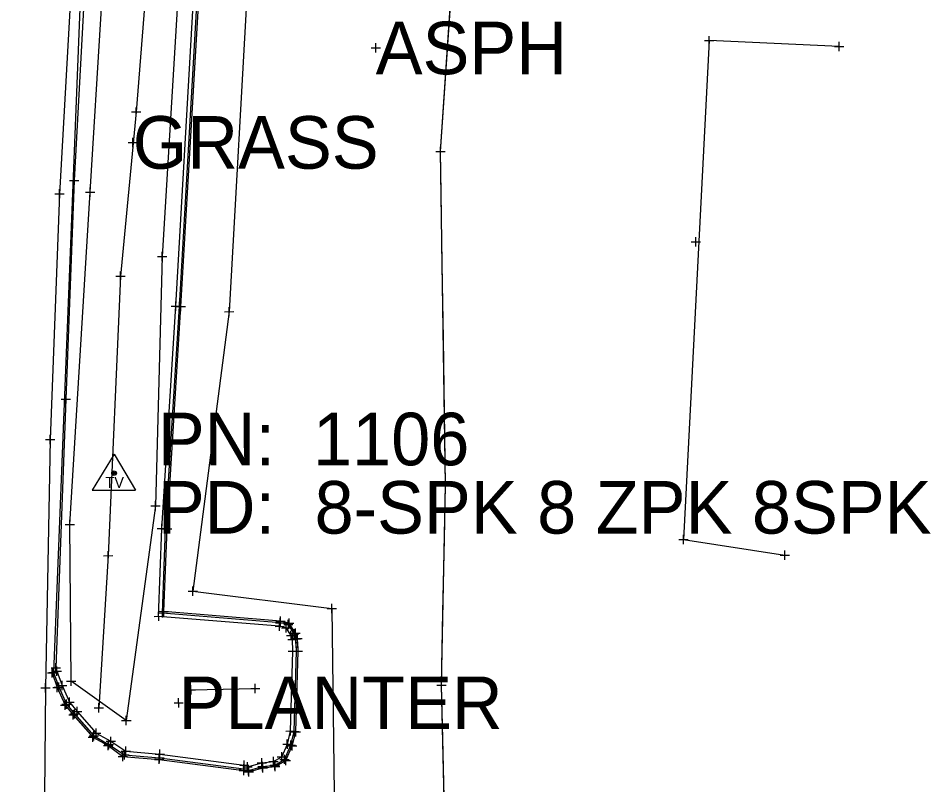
# Model space of a CAD drawing. Extents: x -1 to 1157254, y -1 to 2021979.
# Drawn here: x 1151704.9 to 1151829.9, y 2019737 to 2019842 of the extents above; entities that cross this region are included whole.
import ezdxf

# ---------------------------------------------------------------- set-up
doc = ezdxf.new("R2010")
doc.units = 0
for name, color, linetype in [('S_BREAKLINE', 7, 'Continuous'), ('S_BUILDING_ANNOT', 7, 'Continuous'), ('S_CTL_TABLE', 7, 'Continuous'), ('S_DTM_PAVEMENT', 7, 'Continuous'), ('S_EDGE_BITUMINOUS_ANNOT', 7, 'Continuous'), ('S_EDGE_CONCRETE', 7, 'Continuous'), ('S_EDGE_PAVEMENT', 7, 'Continuous'), ('S_EDGE_PAVEMENT_ANNOT', 7, 'Continuous'), ('S_ENV_CONSTRAINT', 7, 'Continuous'), ('S_FLAG_POLE_ANNOT', 7, 'Continuous'), ('S_GAS_PUMP_ISLAND_ANNOT', 7, 'Continuous'), ('S_GAS_UTILITIES_ANNOT', 7, 'Continuous'), ('S_GATE', 7, 'Continuous')]:
    doc.layers.add(name, color=color, linetype=linetype)

msp = doc.modelspace()

# ---------------------------------------------------------------- linework, layer by layer
at = {"layer": 'S_BREAKLINE'}
for p, q in [((1151717.99, 2019782.25), (1151714.98, 2019777.3)), ((1151717.99, 2019782.25), (1151720.94, 2019777.3)), ((1151714.98, 2019777.3), (1151720.94, 2019777.3))]:
    msp.add_line(p, q, dxfattribs=at)
for radius in [0.311, 0.183, 0.103]:
    msp.add_circle((1151717.99, 2019779.64), radius, dxfattribs=at)
at = {"layer": 'S_BUILDING_ANNOT'}
for p, q in [((1151799.54, 2019838.25), (1151799.54, 2019839.52)), ((1151753.84, 2019837.26), (1151753.84, 2019838.53)), ((1151798.9, 2019838.89), (1151800.18, 2019838.89)), ((1151799.54, 2019838.89), (1151799.54, 2019838.89)), ((1151817.36, 2019837.47), (1151817.35, 2019838.74)), ((1151753.21, 2019837.89), (1151754.48, 2019837.89)), ((1151753.84, 2019837.89), (1151753.84, 2019837.89)), ((1151816.72, 2019838.1), (1151817.99, 2019838.1)), ((1151817.36, 2019838.1), (1151817.36, 2019838.1)), ((1151719.9, 2019824.94), (1151721.18, 2019824.95)), ((1151720.54, 2019824.31), (1151720.54, 2019825.58)), ((1151720.54, 2019824.95), (1151720.54, 2019824.95)), ((1151711.87, 2019819.72), (1151713.14, 2019819.72)), ((1151712.5, 2019819.08), (1151712.5, 2019820.36)), ((1151712.5, 2019819.72), (1151712.5, 2019819.72)), ((1151710.53, 2019817.26), (1151710.53, 2019818.53)), ((1151709.89, 2019817.9), (1151711.17, 2019817.9)), ((1151710.53, 2019817.9), (1151710.53, 2019817.9)), ((1151797.7, 2019810.7), (1151797.7, 2019811.97)), ((1151797.07, 2019811.34), (1151798.34, 2019811.34)), ((1151797.7, 2019811.34), (1151797.7, 2019811.34)), ((1151726.45, 2019801.88), (1151726.45, 2019803.15)), ((1151726.95, 2019801.85), (1151726.95, 2019803.12)), ((1151727.15, 2019801.84), (1151727.15, 2019803.11)), ((1151725.82, 2019802.51), (1151727.09, 2019802.51)), ((1151726.32, 2019802.48), (1151727.59, 2019802.48)), ((1151726.45, 2019802.51), (1151726.45, 2019802.51)), ((1151726.51, 2019802.47), (1151727.79, 2019802.47)), ((1151726.95, 2019802.48), (1151726.95, 2019802.48)), ((1151727.15, 2019802.47), (1151727.15, 2019802.47)), ((1151710.74, 2019789.77), (1151712.02, 2019789.77)), ((1151711.38, 2019789.13), (1151711.38, 2019790.41)), ((1151711.38, 2019789.77), (1151711.38, 2019789.77)), ((1151709.24, 2019783.62), (1151709.24, 2019784.89)), ((1151708.61, 2019784.25), (1151709.88, 2019784.26)), ((1151709.24, 2019784.25), (1151709.24, 2019784.25)), ((1151723.91, 2019772.05), (1151725.19, 2019772.05)), ((1151724.41, 2019772.03), (1151725.69, 2019772.03)), ((1151724.55, 2019771.42), (1151724.55, 2019772.69)), ((1151724.55, 2019772.05), (1151724.55, 2019772.05)), ((1151724.61, 2019772.02), (1151725.89, 2019772.02)), ((1151725.05, 2019771.39), (1151725.05, 2019772.66)), ((1151725.05, 2019772.03), (1151725.05, 2019772.03)), ((1151725.25, 2019771.38), (1151725.25, 2019772.65)), ((1151725.25, 2019772.02), (1151725.25, 2019772.02)), ((1151796.01, 2019769.93), (1151796.01, 2019771.2)), ((1151795.38, 2019770.56), (1151796.65, 2019770.56)), ((1151796.01, 2019770.56), (1151796.01, 2019770.56)), ((1151809.28, 2019768.42), (1151810.56, 2019768.42)), ((1151809.92, 2019767.78), (1151809.92, 2019769.06)), ((1151809.92, 2019768.42), (1151809.92, 2019768.42)), ((1151724.11, 2019759.39), (1151724.1, 2019760.66)), ((1151724.19, 2019760.67), (1151725.47, 2019760.67)), ((1151724.62, 2019759.85), (1151724.62, 2019761.12)), ((1151724.83, 2019760.03), (1151724.83, 2019761.3)), ((1151724.83, 2019760.67), (1151724.83, 2019760.67)), ((1151723.47, 2019760.02), (1151724.74, 2019760.03)), ((1151723.99, 2019760.48), (1151725.26, 2019760.49)), ((1151724.1, 2019760.02), (1151724.1, 2019760.02)), ((1151724.62, 2019760.48), (1151724.62, 2019760.48)), ((1151740.15, 2019759.35), (1151741.42, 2019759.35)), ((1151740.76, 2019758.52), (1151740.76, 2019759.79)), ((1151740.79, 2019758.71), (1151740.78, 2019759.99)), ((1151740.79, 2019759.35), (1151740.79, 2019759.35)), ((1151741.88, 2019758.28), (1151741.87, 2019759.55)), ((1151742, 2019758.45), (1151742, 2019759.73)), ((1151740.05, 2019758.65), (1151741.32, 2019758.66)), ((1151740.12, 2019759.15), (1151741.39, 2019759.15)), ((1151740.68, 2019758.02), (1151740.68, 2019759.29)), ((1151740.68, 2019758.66), (1151740.68, 2019758.66)), ((1151740.76, 2019759.15), (1151740.76, 2019759.15)), ((1151740.93, 2019758.47), (1151742.2, 2019758.47)), ((1151741.24, 2019758.91), (1151742.51, 2019758.91)), ((1151741.36, 2019759.09), (1151742.64, 2019759.09)), ((1151741.57, 2019757.83), (1151741.56, 2019759.1)), ((1151741.56, 2019758.47), (1151741.56, 2019758.47)), ((1151741.88, 2019758.91), (1151741.88, 2019758.91)), ((1151742, 2019759.09), (1151742, 2019759.09)), ((1151742.69, 2019756.98), (1151742.69, 2019758.26)), ((1151742.87, 2019757.07), (1151742.87, 2019758.34)), ((1151741.6, 2019757.4), (1151742.87, 2019757.4)), ((1151741.79, 2019756.84), (1151743.06, 2019756.84)), ((1151742.06, 2019757.62), (1151743.33, 2019757.62)), ((1151742.24, 2019756.77), (1151742.23, 2019758.04)), ((1151742.24, 2019757.7), (1151743.51, 2019757.71)), ((1151742.24, 2019757.4), (1151742.24, 2019757.4)), ((1151742.28, 2019756.93), (1151743.55, 2019756.94)), ((1151742.42, 2019756.21), (1151742.42, 2019757.48)), ((1151742.42, 2019756.84), (1151742.42, 2019756.84)), ((1151742.48, 2019756.97), (1151743.75, 2019756.97)), ((1151742.69, 2019757.62), (1151742.69, 2019757.62)), ((1151742.87, 2019757.7), (1151742.87, 2019757.7)), ((1151742.92, 2019756.3), (1151742.92, 2019757.57)), ((1151742.92, 2019756.93), (1151742.92, 2019756.93)), ((1151743.12, 2019756.34), (1151743.12, 2019757.61)), ((1151743.12, 2019756.97), (1151743.12, 2019756.97)), ((1151742.5, 2019754.62), (1151742.5, 2019755.89)), ((1151743, 2019754.62), (1151743, 2019755.89)), ((1151743.2, 2019754.62), (1151743.2, 2019755.9)), ((1151741.86, 2019755.25), (1151743.13, 2019755.26)), ((1151742.36, 2019755.26), (1151743.63, 2019755.26)), ((1151742.5, 2019755.25), (1151742.5, 2019755.25)), ((1151742.56, 2019755.26), (1151743.83, 2019755.26)), ((1151743, 2019755.26), (1151743, 2019755.26)), ((1151743.2, 2019755.26), (1151743.2, 2019755.26)), ((1151709.99, 2019752.33), (1151709.99, 2019753.6)), ((1151710.16, 2019751.88), (1151710.16, 2019753.15)), ((1151708.87, 2019752.28), (1151710.14, 2019752.29)), ((1151709.05, 2019752.35), (1151710.33, 2019752.35)), ((1151709.36, 2019752.96), (1151710.63, 2019752.97)), ((1151709.5, 2019751.65), (1151709.5, 2019752.92)), ((1151709.5, 2019752.29), (1151709.5, 2019752.29)), ((1151709.53, 2019752.52), (1151710.8, 2019752.52)), ((1151709.69, 2019751.72), (1151709.69, 2019752.99)), ((1151709.69, 2019752.35), (1151709.69, 2019752.35)), ((1151709.99, 2019752.96), (1151709.99, 2019752.96)), ((1151710.16, 2019752.52), (1151710.16, 2019752.52)), ((1151708.59, 2019749.61), (1151708.58, 2019750.89)), ((1151710.21, 2019749.64), (1151710.21, 2019750.91)), ((1151710.4, 2019749.71), (1151710.4, 2019750.98)), ((1151710.86, 2019749.9), (1151710.86, 2019751.17)), ((1151728.54, 2019749.34), (1151728.53, 2019750.61)), ((1151737.34, 2019749.49), (1151737.34, 2019750.76)), ((1151707.95, 2019750.25), (1151709.22, 2019750.25)), ((1151708.59, 2019750.25), (1151708.59, 2019750.25)), ((1151709.58, 2019750.27), (1151710.85, 2019750.27)), ((1151709.76, 2019750.34), (1151711.04, 2019750.35)), ((1151710.21, 2019750.27), (1151710.21, 2019750.27)), ((1151710.23, 2019750.53), (1151711.5, 2019750.53)), ((1151710.4, 2019750.35), (1151710.4, 2019750.35)), ((1151710.86, 2019750.53), (1151710.86, 2019750.53)), ((1151727.9, 2019749.97), (1151729.17, 2019749.98)), ((1151728.54, 2019749.97), (1151728.54, 2019749.97)), ((1151736.71, 2019750.13), (1151737.98, 2019750.13)), ((1151737.34, 2019750.13), (1151737.34, 2019750.13)), ((1151711.25, 2019748.25), (1151712.52, 2019748.25)), ((1151711.28, 2019747.24), (1151711.28, 2019748.51)), ((1151711.45, 2019747.35), (1151711.45, 2019748.62)), ((1151711.88, 2019747.61), (1151711.88, 2019748.89)), ((1151711.88, 2019748.25), (1151711.88, 2019748.25)), ((1151726.21, 2019748.18), (1151727.48, 2019748.18)), ((1151726.85, 2019747.54), (1151726.84, 2019748.82)), ((1151726.84, 2019748.18), (1151726.84, 2019748.18)), ((1151710.65, 2019747.88), (1151711.92, 2019747.88)), ((1151710.82, 2019747.98), (1151712.09, 2019747.99)), ((1151711.28, 2019747.88), (1151711.28, 2019747.88)), ((1151711.45, 2019747.98), (1151711.45, 2019747.98)), ((1151712.3, 2019746.97), (1151713.57, 2019746.97)), ((1151712.4, 2019745.88), (1151712.4, 2019747.15)), ((1151712.56, 2019746.01), (1151712.55, 2019747.28)), ((1151712.94, 2019746.34), (1151712.93, 2019747.61)), ((1151712.93, 2019746.97), (1151712.93, 2019746.97)), ((1151711.77, 2019746.52), (1151713.04, 2019746.52)), ((1151711.92, 2019746.65), (1151713.19, 2019746.65)), ((1151712.4, 2019746.52), (1151712.4, 2019746.52)), ((1151712.55, 2019746.65), (1151712.55, 2019746.65)), ((1151715.55, 2019743.4), (1151715.54, 2019744.67)), ((1151741.55, 2019744.31), (1151742.83, 2019744.32)), ((1151742.19, 2019743.68), (1151742.19, 2019744.95)), ((1151742.69, 2019743.61), (1151742.69, 2019744.88)), ((1151742.89, 2019743.58), (1151742.89, 2019744.85)), ((1151714.46, 2019743.48), (1151715.73, 2019743.48)), ((1151714.59, 2019743.64), (1151715.86, 2019743.64)), ((1151714.91, 2019744.03), (1151716.18, 2019744.04)), ((1151715.1, 2019742.85), (1151715.1, 2019744.12)), ((1151715.1, 2019743.48), (1151715.1, 2019743.48)), ((1151715.23, 2019743), (1151715.22, 2019744.28)), ((1151715.23, 2019743.64), (1151715.23, 2019743.64)), ((1151715.54, 2019744.04), (1151715.54, 2019744.04)), ((1151717.28, 2019741.85), (1151717.28, 2019743.12)), ((1151717.54, 2019742.27), (1151717.54, 2019743.54)), ((1151741.74, 2019741.89), (1151741.73, 2019743.16)), ((1151742.05, 2019744.24), (1151743.32, 2019744.25)), ((1151742.19, 2019744.31), (1151742.19, 2019744.31)), ((1151742.25, 2019744.22), (1151743.52, 2019744.22)), ((1151742.69, 2019744.24), (1151742.69, 2019744.24)), ((1151742.89, 2019744.22), (1151742.89, 2019744.22)), ((1151716.54, 2019742.31), (1151717.81, 2019742.31)), ((1151716.64, 2019742.48), (1151717.91, 2019742.48)), ((1151716.9, 2019742.91), (1151718.17, 2019742.91)), ((1151717.17, 2019741.67), (1151717.17, 2019742.95)), ((1151717.17, 2019742.31), (1151717.17, 2019742.31)), ((1151717.28, 2019742.48), (1151717.28, 2019742.48)), ((1151717.54, 2019742.91), (1151717.54, 2019742.91)), ((1151719.58, 2019740.91), (1151719.58, 2019742.18)), ((1151741.1, 2019742.53), (1151742.37, 2019742.53)), ((1151741.57, 2019742.36), (1151742.85, 2019742.37)), ((1151741.74, 2019742.53), (1151741.74, 2019742.53)), ((1151741.76, 2019742.3), (1151743.04, 2019742.3)), ((1151742.21, 2019741.73), (1151742.21, 2019743)), ((1151742.21, 2019742.37), (1151742.21, 2019742.37)), ((1151742.4, 2019741.66), (1151742.4, 2019742.94)), ((1151742.4, 2019742.3), (1151742.4, 2019742.3)), ((1151718.56, 2019740.82), (1151719.83, 2019740.82)), ((1151718.78, 2019741.06), (1151720.05, 2019741.06)), ((1151718.95, 2019741.54), (1151720.22, 2019741.55)), ((1151719.2, 2019740.19), (1151719.19, 2019741.46)), ((1151719.19, 2019740.82), (1151719.19, 2019740.82)), ((1151719.41, 2019740.42), (1151719.41, 2019741.69)), ((1151719.41, 2019741.06), (1151719.41, 2019741.06)), ((1151719.58, 2019741.55), (1151719.58, 2019741.55)), ((1151723.57, 2019740.63), (1151724.84, 2019740.63)), ((1151723.63, 2019741.13), (1151724.9, 2019741.13)), ((1151724.19, 2019739.8), (1151724.19, 2019741.07)), ((1151724.21, 2019740), (1151724.21, 2019741.27)), ((1151724.21, 2019740.63), (1151724.21, 2019740.63)), ((1151724.26, 2019740.49), (1151724.26, 2019741.77)), ((1151724.26, 2019741.13), (1151724.26, 2019741.13)), ((1151738.23, 2019739.32), (1151738.23, 2019740.59)), ((1151739.85, 2019739.48), (1151739.85, 2019740.76)), ((1151740.33, 2019740.78), (1151741.6, 2019740.78)), ((1151740.97, 2019740.14), (1151740.97, 2019741.42)), ((1151740.97, 2019740.78), (1151740.97, 2019740.78)), ((1151741.36, 2019739.8), (1151741.36, 2019741.07)), ((1151741.52, 2019739.66), (1151741.52, 2019740.93)), ((1151723.55, 2019740.43), (1151724.82, 2019740.43)), ((1151724.19, 2019740.43), (1151724.19, 2019740.43)), ((1151735.21, 2019739.62), (1151736.48, 2019739.63)), ((1151735.64, 2019739.4), (1151736.91, 2019739.4)), ((1151735.75, 2019738.29), (1151735.75, 2019739.57)), ((1151735.78, 2019738.49), (1151735.78, 2019739.76)), ((1151735.84, 2019738.99), (1151735.84, 2019740.26)), ((1151735.84, 2019739.62), (1151735.84, 2019739.62)), ((1151736.27, 2019738.76), (1151736.27, 2019740.04)), ((1151736.27, 2019739.4), (1151736.27, 2019739.4)), ((1151736.41, 2019738.28), (1151736.41, 2019739.55)), ((1151736.47, 2019738.09), (1151736.46, 2019739.36)), ((1151737.6, 2019739.96), (1151738.87, 2019739.96)), ((1151737.69, 2019739.46), (1151738.96, 2019739.47)), ((1151738.23, 2019739.96), (1151738.23, 2019739.96)), ((1151738.33, 2019738.83), (1151738.33, 2019740.1)), ((1151738.33, 2019739.47), (1151738.33, 2019739.47)), ((1151738.37, 2019738.63), (1151738.36, 2019739.9)), ((1151739.21, 2019740.12), (1151740.48, 2019740.12)), ((1151739.37, 2019739.63), (1151740.64, 2019739.64)), ((1151739.43, 2019739.44), (1151740.71, 2019739.44)), ((1151739.85, 2019740.12), (1151739.85, 2019740.12)), ((1151740.01, 2019739), (1151740, 2019740.27)), ((1151740.01, 2019739.63), (1151740.01, 2019739.63)), ((1151740.07, 2019738.8), (1151740.07, 2019740.08)), ((1151740.07, 2019739.44), (1151740.07, 2019739.44)), ((1151740.72, 2019740.43), (1151742, 2019740.43)), ((1151740.88, 2019740.29), (1151742.15, 2019740.29)), ((1151741.36, 2019740.43), (1151741.36, 2019740.43)), ((1151741.52, 2019740.29), (1151741.52, 2019740.29)), ((1151735.12, 2019738.93), (1151736.39, 2019738.93)), ((1151735.14, 2019739.13), (1151736.41, 2019739.13)), ((1151735.75, 2019738.93), (1151735.75, 2019738.93)), ((1151735.77, 2019738.92), (1151737.05, 2019738.92)), ((1151735.78, 2019739.13), (1151735.78, 2019739.13)), ((1151735.83, 2019738.72), (1151737.1, 2019738.73)), ((1151736.41, 2019738.92), (1151736.41, 2019738.92)), ((1151736.47, 2019738.73), (1151736.47, 2019738.73)), ((1151737.73, 2019739.27), (1151739, 2019739.27)), ((1151738.36, 2019739.27), (1151738.36, 2019739.27))]:
    msp.add_line(p, q, dxfattribs=at)
at = {"layer": 'S_CTL_TABLE'}
for p, q in [((1151721.03, 2019828.48), (1151721.02, 2019829.75)), ((1151720.39, 2019829.12), (1151721.66, 2019829.12)), ((1151721.02, 2019829.12), (1151721.02, 2019829.12)), ((1151762.73, 2019823.08), (1151762.73, 2019824.36)), ((1151762.1, 2019823.72), (1151763.37, 2019823.72)), ((1151762.73, 2019823.72), (1151762.73, 2019823.72)), ((1151714.08, 2019818.15), (1151715.35, 2019818.15)), ((1151714.72, 2019817.51), (1151714.72, 2019818.79)), ((1151714.72, 2019818.15), (1151714.72, 2019818.15)), ((1151724.6, 2019808.68), (1151724.59, 2019809.95)), ((1151723.96, 2019809.31), (1151725.23, 2019809.32)), ((1151724.6, 2019809.32), (1151724.6, 2019809.32)), ((1151718.89, 2019805.98), (1151718.89, 2019807.26)), ((1151718.25, 2019806.62), (1151719.53, 2019806.62)), ((1151718.89, 2019806.62), (1151718.89, 2019806.62)), ((1151733.75, 2019801.13), (1151733.75, 2019802.4)), ((1151733.11, 2019801.76), (1151734.38, 2019801.77)), ((1151733.75, 2019801.77), (1151733.75, 2019801.77)), ((1151763.43, 2019777.41), (1151763.43, 2019778.69)), ((1151762.79, 2019778.05), (1151764.06, 2019778.05)), ((1151763.43, 2019778.05), (1151763.43, 2019778.05)), ((1151723.68, 2019774.52), (1151723.67, 2019775.8)), ((1151723.04, 2019775.16), (1151724.31, 2019775.16)), ((1151723.67, 2019775.16), (1151723.67, 2019775.16)), ((1151711.94, 2019771.96), (1151711.94, 2019773.23)), ((1151711.31, 2019772.6), (1151712.58, 2019772.6)), ((1151711.94, 2019772.6), (1151711.94, 2019772.6)), ((1151716.56, 2019768.33), (1151717.83, 2019768.34)), ((1151717.2, 2019767.7), (1151717.19, 2019768.97)), ((1151717.2, 2019768.34), (1151717.2, 2019768.34)), ((1151728.14, 2019763.49), (1151729.41, 2019763.49)), ((1151728.78, 2019762.85), (1151728.77, 2019764.13)), ((1151728.77, 2019763.49), (1151728.77, 2019763.49)), ((1151747.21, 2019761.12), (1151748.48, 2019761.12)), ((1151747.84, 2019760.48), (1151747.84, 2019761.76)), ((1151747.84, 2019761.12), (1151747.84, 2019761.12)), ((1151711.47, 2019751.13), (1151712.74, 2019751.13)), ((1151712.11, 2019750.5), (1151712.11, 2019751.77)), ((1151712.11, 2019751.13), (1151712.11, 2019751.13)), ((1151762.22, 2019750.6), (1151763.49, 2019750.61)), ((1151762.86, 2019749.97), (1151762.85, 2019751.24)), ((1151762.86, 2019750.61), (1151762.86, 2019750.61)), ((1151715.9, 2019746.84), (1151715.9, 2019748.11)), ((1151715.26, 2019747.47), (1151716.53, 2019747.47)), ((1151715.9, 2019747.47), (1151715.9, 2019747.47)), ((1151719.03, 2019745.76), (1151720.31, 2019745.77)), ((1151719.67, 2019745.13), (1151719.67, 2019746.4)), ((1151719.67, 2019745.76), (1151719.67, 2019745.76))]:
    msp.add_line(p, q, dxfattribs=at)
at = {"layer": 'S_DTM_PAVEMENT'}
msp.add_lwpolyline([(1151728.54, 2019749.97), (1151737.34, 2019750.13)], dxfattribs=at)
at = {"layer": 'S_EDGE_BITUMINOUS_ANNOT'}
for points in [[(1151729.38, 2019894.61), (1151725.75, 2019887.85), (1151723.93, 2019866.05), (1151721.02, 2019829.12), (1151718.89, 2019806.62), (1151717.2, 2019768.34), (1151715.9, 2019747.47)], [(1151764.61, 2019691.37), (1151763.49, 2019723.26), (1151762.86, 2019750.61), (1151763.43, 2019778.05), (1151762.73, 2019823.72), (1151767.49, 2019894.33)], [(1151728.96, 2019880.81), (1151727.14, 2019851.61), (1151724.6, 2019809.32), (1151723.67, 2019775.16), (1151719.67, 2019745.76), (1151712.11, 2019751.13), (1151711.94, 2019772.6), (1151714.72, 2019818.15), (1151717.71, 2019867.12), (1151719.64, 2019883.55)], [(1151737.74, 2019878.18), (1151736.38, 2019848.21), (1151733.75, 2019801.77), (1151728.77, 2019763.49), (1151747.84, 2019761.12), (1151748.14, 2019735.82)]]:
    msp.add_lwpolyline(points, dxfattribs=at)
at = {"layer": 'S_EDGE_CONCRETE'}
msp.add_lwpolyline([(1151721.2, 2020067.58), (1151720.35, 2020034.81), (1151718.96, 2020003.33), (1151717.56, 2019973.57), (1151716.63, 2019939.58), (1151714.65, 2019898.33), (1151714.71, 2019888.07), (1151712.7, 2019856.91), (1151710.53, 2019817.9), (1151709.24, 2019784.25), (1151708.59, 2019750.25), (1151708.31, 2019720.95), (1151707.21, 2019690.49), (1151706.05, 2019655.66), (1151705.36, 2019633.56), (1151704.86, 2019608.44), (1151705.24, 2019577.73)], dxfattribs=at)
at = {"layer": 'S_EDGE_PAVEMENT'}
for points in [[(1151736.27, 2019739.4), (1151738.23, 2019739.96), (1151739.85, 2019740.12), (1151740.97, 2019740.78), (1151741.74, 2019742.53), (1151742.19, 2019744.31), (1151742.5, 2019755.25), (1151742.42, 2019756.84), (1151742.24, 2019757.4), (1151741.56, 2019758.47), (1151740.68, 2019758.66), (1151724.1, 2019760.02), (1151724.55, 2019772.05), (1151726.45, 2019802.51), (1151728.8, 2019842.99), (1151731.01, 2019880.62), (1151749.92, 2019879.66), (1151752.39, 2019879.76), (1151753.54, 2019880.38), (1151754.05, 2019880.78), (1151754.47, 2019881.5), (1151755.76, 2019898.72), (1151787.95, 2019896.81), (1151823.96, 2019894.76)], [(1151736.41, 2019738.92), (1151738.33, 2019739.47), (1151740.01, 2019739.63), (1151741.36, 2019740.43), (1151742.21, 2019742.37), (1151742.69, 2019744.24), (1151743, 2019755.26), (1151742.92, 2019756.93), (1151742.69, 2019757.62), (1151741.88, 2019758.91), (1151740.76, 2019759.15), (1151724.62, 2019760.48), (1151725.05, 2019772.03), (1151726.95, 2019802.48), (1151729.3, 2019842.97), (1151731.48, 2019880.1), (1151749.92, 2019879.16), (1151752.52, 2019879.27), (1151753.81, 2019879.96), (1151754.43, 2019880.45), (1151754.96, 2019881.35), (1151756.22, 2019898.19), (1151787.92, 2019896.31), (1151823.93, 2019894.26)], [(1151715.53, 2019885.43), (1151714.64, 2019876.78), (1151709.69, 2019752.35), (1151710.4, 2019750.35), (1151711.45, 2019747.98), (1151712.55, 2019746.65), (1151715.23, 2019743.64), (1151717.28, 2019742.48), (1151719.41, 2019741.06), (1151724.21, 2019740.63)], [(1151715.74, 2019876.27), (1151714.44, 2019855.08), (1151712.5, 2019819.72), (1151711.38, 2019789.77), (1151709.99, 2019752.96)], [(1151709.69, 2019752.35), (1151710.4, 2019750.35), (1151711.45, 2019747.98), (1151712.55, 2019746.65), (1151715.23, 2019743.64), (1151717.28, 2019742.48), (1151719.41, 2019741.06), (1151724.21, 2019740.63), (1151735.78, 2019739.13)], [(1151710.16, 2019752.52), (1151710.86, 2019750.53), (1151711.88, 2019748.25), (1151712.93, 2019746.97), (1151715.54, 2019744.04), (1151717.54, 2019742.91), (1151719.58, 2019741.55), (1151724.26, 2019741.13), (1151735.84, 2019739.62)]]:
    msp.add_lwpolyline(points, dxfattribs=at)
at = {"layer": 'S_EDGE_PAVEMENT_ANNOT'}
msp.add_lwpolyline([(1151736.47, 2019738.73), (1151738.36, 2019739.27), (1151740.07, 2019739.44), (1151741.52, 2019740.29), (1151742.4, 2019742.3), (1151742.89, 2019744.22), (1151743.2, 2019755.26), (1151743.12, 2019756.97), (1151742.87, 2019757.7), (1151742, 2019759.09), (1151740.79, 2019759.35), (1151724.83, 2019760.67), (1151725.25, 2019772.02), (1151727.15, 2019802.47), (1151729.5, 2019842.95), (1151731.67, 2019879.89), (1151749.92, 2019878.95), (1151752.58, 2019879.07), (1151753.92, 2019879.79), (1151754.58, 2019880.31), (1151755.16, 2019881.28), (1151756.4, 2019897.98), (1151787.91, 2019896.11), (1151823.92, 2019894.06)], dxfattribs=at)
at = {"layer": 'S_ENV_CONSTRAINT'}
msp.add_lwpolyline([(1151709.5, 2019752.29), (1151710.21, 2019750.27), (1151711.28, 2019747.88), (1151712.4, 2019746.52), (1151715.1, 2019743.48), (1151717.17, 2019742.31), (1151719.19, 2019740.82), (1151724.19, 2019740.43), (1151735.75, 2019738.93)], dxfattribs=at)
at = {"layer": 'S_FLAG_POLE_ANNOT'}
msp.add_lwpolyline([(1151817.36, 2019838.1), (1151799.54, 2019838.89), (1151796.01, 2019770.56), (1151809.92, 2019768.42)], dxfattribs=at)
at = {"layer": 'S_GAS_PUMP_ISLAND_ANNOT'}
msp.add_lwpolyline([(1151763.26, 2019733.25), (1151763.03, 2019743.25), (1151762.86, 2019750.61), (1151763.06, 2019760.6), (1151763.27, 2019770.6), (1151763.43, 2019778.05), (1151763.27, 2019788.05), (1151763.12, 2019798.05), (1151762.97, 2019808.05), (1151762.82, 2019818.04), (1151762.73, 2019823.72), (1151763.4, 2019833.7), (1151764.08, 2019843.67)], dxfattribs=at)

# ---------------------------------------------------------------- texts
at = {"layer": 'S_BREAKLINE'}
msp.add_text('TV', height=1.499, dxfattribs=at).set_placement((1151716.79, 2019777.63))
at = {"layer": 'S_GAS_UTILITIES_ANNOT'}
for s, p in [('PN: ', (1151723.99, 2019780.72)), ('1106', (1151745.26, 2019780.72)), ('PD: ', (1151723.99, 2019771.36)), ('8-SPK 8 ZPK 8SPK', (1151745.47, 2019771.36))]:
    msp.add_text(s, height=7.2, dxfattribs=at).set_placement(p)
at = {"layer": 'S_GATE'}
for s, p in [('ASPH', (1151753.84, 2019834.29)), ('GRASS', (1151720.54, 2019821.35)), ('PLANTER', (1151726.84, 2019744.58))]:
    msp.add_text(s, height=7.2, dxfattribs=at).set_placement(p)

doc.saveas('drawing.dxf')
